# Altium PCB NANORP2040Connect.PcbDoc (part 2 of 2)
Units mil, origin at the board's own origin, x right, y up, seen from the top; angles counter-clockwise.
Board outline 1700 x 700 mil, 4 copper layers (TOP, GND, SIG, BOTTOM), stack 62.441 mil thick; 92 components, 78 nets, 400 pads, 196 vias.
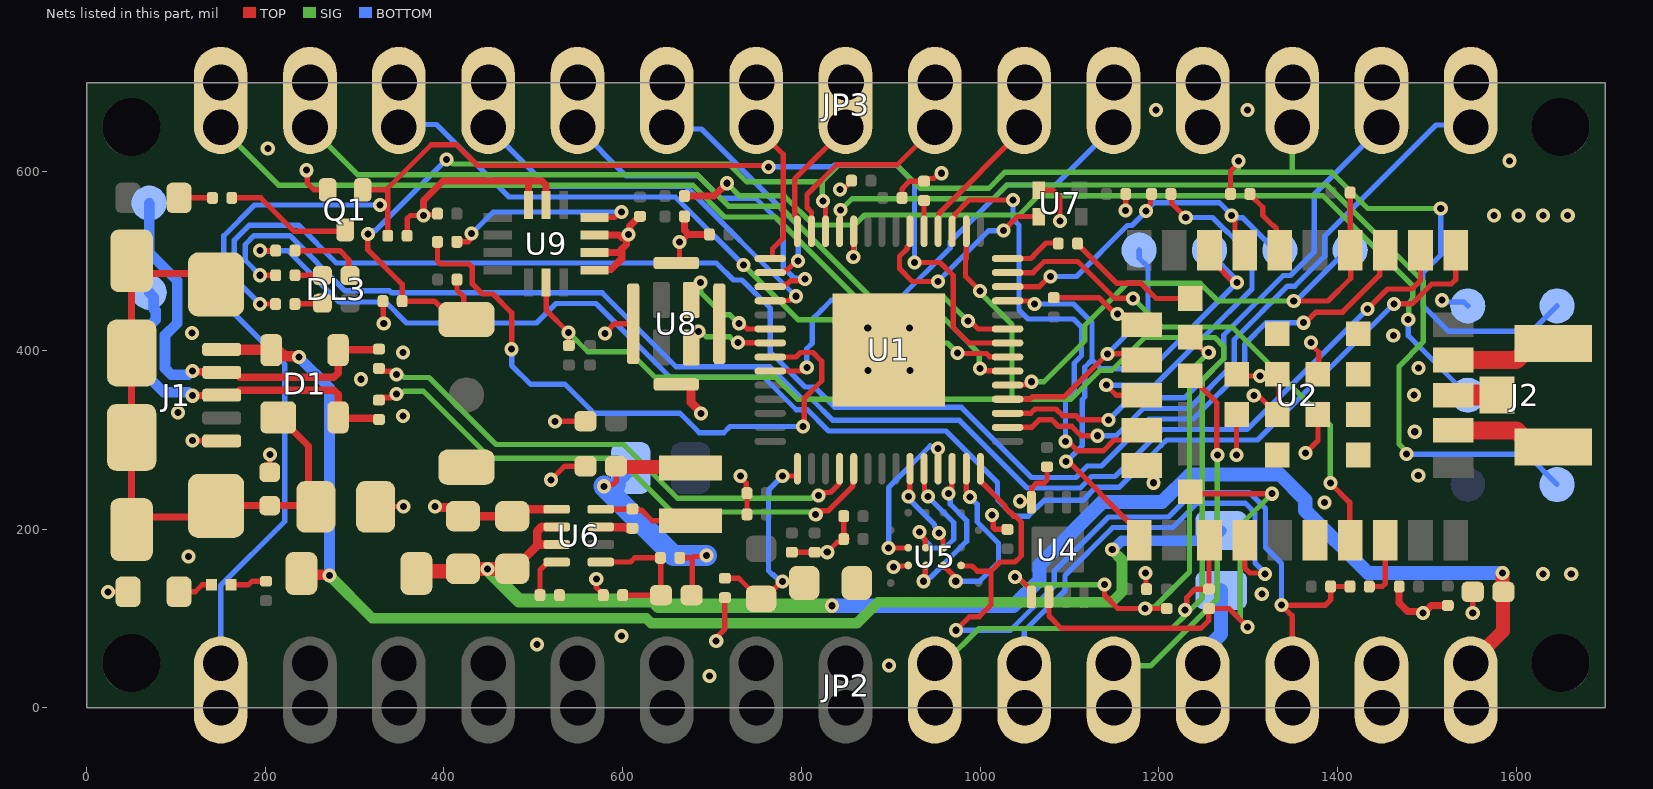
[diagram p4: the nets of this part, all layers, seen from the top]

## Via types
v1: diameter 15.75, hole 7.87, TOP to BOTTOM, tented both sides, 196 vias

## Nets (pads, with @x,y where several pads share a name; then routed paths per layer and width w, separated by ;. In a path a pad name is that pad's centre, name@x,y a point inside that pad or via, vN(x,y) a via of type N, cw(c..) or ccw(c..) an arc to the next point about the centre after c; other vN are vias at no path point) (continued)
A5/SCL~: JP2.9 R10.1 R17.1 U1.16 U2.3 U9.13 | length 1810
  TOP w5.91: U9.13@514.34,476.13 514.38,476.09 514.38,445.21 539.67,419.93 539.67,405.61 R10.1@539.76,405.51 ; U1.16@984.64,533.47 984.64,502.76 983.72,501.83 983.72,483.15 v1(1000.02,466.85) ; v1(1229.53,109.48) 1231.41,111.36 1231.41,123.54 1240.75,132.87 R17.1@1256.3,132.87 1256.3,187.01 U2.3@1256.89,187.6
  SIG w5.91: v1(539.57,420.03) 560.98,398.62 607.7,398.62 636.25,370.08 771.12,370.08 795.72,345.47 1035.82,345.47 ; JP2.9@949.41,50 959.84,50 998.7,88.86 1214.68,88.86 v1@1231.65,105.83 ; v1(1000.02,466.85) 1000.02,464.98 1035.82,429.17 1035.82,345.47 ; v1(1229.53,109.48) 1231.65,107.35 1233.17,107.35 1248.91,123.09 1248.91,366.96 1272.76,390.82 1272.76,404.68 1262.96,414.48 1184.35,414.48 1147.8,377.94 1134.42,377.94 1101.96,345.47 1035.82,345.47
A6: JP2.10 U2.4 | length 497.5
  TOP w5.91: U2.4@1296.26,187.6 1296.26,156.75 1302.12,150.89 1317.56,150.89 v1(1318.85,149.61)
  BOTTOM w5.91: JP2.10@1049.41,50 1049.41,85.73 1095.03,131.35 1095.03,148.15 1148.65,201.77 1215.75,201.77 1243.15,229.17 1296.85,229.17 1307.8,218.22 1307.8,162.22 1318.85,151.16 v1(1318.85,149.61)
A7: JP2.11 U2.34 | length 410.8
  TOP w5.91: U2.34@1235.23,371.65 1264.96,341.92 1264.96,283.69 v1(1265.64,283.01)
  SIG w5.91: JP2.11@1149.41,50 1152.36,47.05 1190.76,47.05 1260.72,117.01 1265.64,121.93 v1(1265.64,283.01)
ANT: J2.SIG U2.13 | length 49.2
  TOP w23.62: U2.13@1529.53,350 J2.SIG@1578.74,350
D2~: JP3.5 U1.37 | length 529.4
  TOP w5.91: U1.37@765.16,376.97 799.45,376.97 803.44,380.96 v1(806.1,380.96)
  BOTTOM w5.91: v1(806.1,380.96) 806.1,402.03 812.14,408.06 812.14,434.83 822.4,445.09 833.55,456.25 907.98,456.25 966.79,515.06 966.79,521.9 1030.04,585.16 1084.57,585.16 JP3.5@1149.41,650
D3~: JP3.6 U1.18 | length 156.4
  TOP w5.91: U1.18@953.15,533.47 953.52,533.84 953.52,553.01 1049.41,648.9 JP3.6@1049.41,650
D4~: JP3.7 U1.27 | length 217.6
  TOP w5.91: U1.27@811.41,533.47 811.41,554.79 806.3,559.91 806.3,574.58 839.68,607.97 907.38,607.97 JP3.7@949.41,650
D5~: JP3.8 U1.28 | length 141.4
  TOP w5.91: U1.28@795.67,533.47 795.67,547.78 792.52,550.92 792.52,591.92 849.41,648.81 JP3.8@849.41,650
D6~: JP3.9 U1.29 | length 166.7
  TOP w5.91: JP3.9@749.41,650 779.79,619.62 779.79,598.48 779.73,598.41 779.73,525.89 767.72,513.88 767.72,503.86 766.06,503.86 U1.29@765.16,502.95
D7~: JP3.10 U1.30 | length 268.9
  TOP w5.91: U1.30@765.16,487.21 779.47,487.21 782.42,490.16 784.23,490.16 794.25,500.18 v1(796.43,500.18)
  BOTTOM w5.91: JP3.10@649.41,650 651.49,647.91 688.27,647.91 796.43,539.75 v1(796.43,500.18)
D8~: JP3.11 U1.31 | length 395.3
  TOP w5.91: U1.31@765.16,471.46 779.47,471.46 782.42,474.41 784.23,474.41 787.95,478.13 802.43,478.13 v1(804.32,480.01)
  BOTTOM w5.91: JP3.11@549.41,650 603.94,595.47 684.78,595.47 709.75,570.5 748.98,570.5 779.73,539.75 779.73,516.51 ; 779.7,516.49 779.7,493.25 791.71,481.23 803.09,481.23 v1(804.32,480.01)
D9~: JP3.12 U1.32 | length 453.7
  TOP w5.91: U1.32@765.16,455.71 765.53,456.09 786.56,456.09 791.21,460.74 v1(793.88,460.74)
  BOTTOM w5.91: JP3.12@449.41,650 515.75,583.66 670.77,583.66 793.7,460.74 v1(793.88,460.74)
D10~: JP3.13 U1.7 | length 790.5
  TOP w5.91: v1(974.8,397.41) 975.56,396.65 1007.08,396.65 1010.64,393.09 1030.53,393.09 U1.7@1030.9,392.72
  SIG w5.91: v1(735.14,495.63) 796.18,434.59 834.84,434.59 860.93,408.5 963.72,408.5 v1(974.8,397.41)
  BOTTOM w5.91: JP3.13@349.41,650 352.36,652.95 391.5,652.95 472.61,571.85 658.92,571.85 v1(735.14,495.63)
D_N: R4.2 U1.46 | length 599.1
  TOP w5.91: v1(819.29,237.86) 821.95,237.86 825.24,241.14 832.46,241.14 842.53,251.21 842.53,267.34 U1.46@842.91,267.72
  TOP w6.3: R4.2@327.16,379.92 330.1,376.98 340.34,376.98 344.29,373.03 v1(346.85,373.03)
  SIG w5.91: v1(346.85,373.03) 348.73,371.15 353.96,371.15 355.23,369.88 383.2,369.88 458.21,294.87 601.2,294.87 661.41,234.66 811,234.66 812.31,235.98 817.41,235.98 v1(819.29,237.86)
D_P: R5.2 U1.47 | length 608.4
  TOP w5.91: v1(816.11,216.44) 818.77,216.44 822.87,220.53 829.94,220.53 857.69,248.28 857.69,251.58 858.28,252.17 858.28,267.34 U1.47@858.66,267.72
  TOP w6.3: R5.2@327.16,344.49 330.1,347.43 v1@340.34,347.43
  SIG w5.91: v1(346.85,351.38) 348.73,353.26 353.96,353.26 355.23,354.53 376.84,354.53 451.85,279.52 594.84,279.52 655.05,219.31 v1@808.98,219.31
GND: C1.1 C2.2 C3.1 C4.1 C5.2 C6.2 C7.2 C8.2 C9.1 C10.2 C11.2 C12.2 C13.2 C14.2 C15.2 C16.2 C17.1 C18.2 C21.2 C22.1 C23.1 C24.2 C25.1 C26.2 C27.2 C28.2 C30.2 C32.2 C33.1 DL1.C J1.5 J2.GND JP2.14 JP3.4 PB1.1 Q1.S R1.1 R3.1 R8.1 R23.1 TP_GND.X U1.GND U2.6 U2.12 U2.14 U2.26 U2.30 U2.GND1 U2.GND2 U2.GND3 U2.GND4 U2.GND5 U2.GND6 U2.GND7 U2.GND8 U2.GND9 U2.GND10 U2.GND11 U2.GND12 U4.4 U5.E4 U6.1 U7.2 U8.5 U9.1 U9.2 U9.3 U9.6 U9.7 | length 2255.1
  TOP w5.91: v1(24.01,129.92) DL1.C@46.26,129.92 ; v1(118.5,299.21) 118.7,299.02 150.98,299.02 J1.5@151.18,298.82 ; R1.1@205,263.7 205.06,263.76 205.06,283.41 v1(205.12,283.46) ; v1(246.06,601.83) 246.89,601 246.89,587.46 254.44,579.92 Q1.S@269.68,579.92 ; C1.1@323.46,225 323.86,225.39 v1(354.72,225.39) ; C2.2@331.56,455.25 332.06,454.75 332.06,430.61 v1(332.56,430.11) ; R23.1@358.72,528.49 358.72,547.72 362.18,551.18 v1(377.23,551.18) ; v1@377.23,552.17 391.73,552.17 C30.2@392.72,553.15 ; v1(519.69,255.31) 534.84,270.47 C3.1@558.46,270.47 ; v1(524.37,320.64) 524.48,320.76 558.35,320.76 C17.1@558.46,320.87 ; v1(570.47,144.49) 570.47,134.77 578.35,126.89 R8.1@578.35,126.18 ; v1(580.05,419.14) 580.05,419.23 590.94,430.12 611.65,430.12 U8.5@611.77,430 ; U8.5@660,497.91 663.62,501.53 v1(663.62,521.49) 665.24,521.49 673.75,530 ; v1(704.72,74.8) 704.72,78.74 714.42,88.44 C8.2@714.42,123.39 ; v1(731.78,259.64) 731.78,257.83 738.44,251.17 738.44,241.07 C18.2@739.21,240.29 739.16,240.24 739.16,216.68 C13.2@739.11,216.63 ; C5.2@789.37,174.21 C6.2@814.96,174.21 v1(829.02,174.21) 840.18,185.37 844.31,185.37 847.44,188.51 C33.1@847.44,188.98 ; v1(843.36,580.25) 845.25,582.14 848.73,582.14 856.21,589.62 C10.2@856.21,590.09 ; C24.2@847.44,214.57 C33.1@847.44,188.98 ; C33.1@851.38,188.98 C33.1@847.44,188.98 ; v1(903.3,157.57) 904.66,158.92 919.16,158.92 U5.E4@919.68,159.45 ; C11.2@912.79,570.87 912.79,580.78 913.51,581.49 913.51,581.81 921.27,589.57 R3.1@937.4,589.57 940.41,592.58 948.18,592.58 954.03,598.43 v1(956.69,598.43) ; v1(1013.63,215.65) 1014.89,214.4 1014.89,201.65 1016.73,199.8 C27.2@1030.71,199.8 ; v1(1044.82,231.31) 1055.31,231.31 1055.31,233.27 1057.48,231.1 U4.4@1057.48,230.12 1058.04,230.68 1058.04,246.37 1063.25,251.57 1071.54,251.57 1075,255.03 C12.2@1075,269.92 ; U7.2@1065.85,579.39 1081.6,579.39 1089.67,571.32 v1(1089.67,544.94) ; C7.2@1082.55,459.17 1114.58,459.17 1133.21,459.17 1151.67,440.7 v1(1153.96,440.7) 1155.09,439.57 1170.27,439.57 U2.26@1181.1,428.74 ; v1(1163.07,556.62) 1163.12,556.67 1163.12,574.75 C14.2@1163.17,574.8 ; U2.30@1181.1,271.26 1183.6,271.26 1194.43,260.43 v1(1194.43,251.97) ; v1(1185.43,151.18) 1185.92,150.69 1185.92,133.37 C26.2@1186.42,132.87 ; v1(1287.29,283.01) 1287.22,283.08 1287.22,327.98 U2.GND11@1287.6,328.35 ; U2.GND12@1287.6,373.62 1289.67,371.55 v1(1313.49,371.55) ; v1(1306.45,349.61) 1308.33,347.72 1313.49,347.72 U2.GND8@1332.87,328.35 1335.04,330.52 1335.04,371.45 U2.GND9@1332.87,373.62 ; v1(1364.54,285.41) 1378.34,299.21 1378.34,328.15 U2.GND5@1378.15,328.35 ; v1(1370.7,409.22) 1370.7,406.56 1379.15,398.1 1379.15,374.63 U2.GND6@1378.15,373.62 ; v1(1551.57,106.3) C25.1@1551.57,129.92
  TOP w7.87: v1(377.23,551.18) 377.23,552.17 377.23,567.98 398.96,589.71 494.65,589.71 ; U9.7@494.65,562.75 494.65,589.71 ; U9.6@514.34,562.75 514.34,585.1 509.73,589.71 494.65,589.71 ; U9.1@568.47,489.91 569.46,490.89 587.14,490.89 598.98,502.73 598.98,513.45 ; U9.2@568.47,509.6 595.13,509.6 598.98,513.45 ; U9.3@568.47,529.28 596.03,529.28 599.09,526.22 v1@604.1,526.22 ; v1(606.42,529.69) 607.92,531.2 607.92,539.31 616.65,548.03 617.24,548.03 C32.2@619.4,550.2 ; v1@607.57,529.69 v1@604.1,526.22 ; C28.2@669.13,550.11 669.13,534.61 673.75,530 C21.2@697.05,530 ; C15.2@1469.25,135.87 1469.25,117.36 1478.81,107.81 1494.16,107.81 v1(1495.67,106.3) 1496.79,106.3 1505.12,114.62 C16.2@1523.62,114.62 ; 598.98,513.45 604.1,518.57 v1@604.1,526.22
  TOP w9.84: v1(390.16,225.39) 391.29,224.26 411.56,224.26 C23.1@421.26,214.57 C4.1@476.38,214.57 484.05,222.24 U6.1@526.18,222.24 ; U8.5@660,362.09 674.39,362.09 676.35,360.12 676.35,342.4 687.75,331.01 v1(687.75,329.72)
  TOP w20: U2.12@1529.53,310.63 1600.4,310.63 1619.1,291.93 J2.GND@1641.73,291.93 ; U2.14@1529.53,389.37 1600.4,389.37 1619.1,408.07 J2.GND@1641.73,408.07
  BOTTOM w5.91: v1(1516.99,456.3) 1518.88,454.42 1541.58,454.42 TP_GND.X@1546,450
  other v1: 697.24,35.43 898.03,47.24 504.33,70.87 598.82,80.6 1315.42,127.5 1630.31,149.61 1661.81,149.61 114.17,169.49 1385.76,229.87 1490.55,260.24 1486.63,309.08 354.33,326.77 102.36,330.71 1485.63,350.39 307.08,367.85 874.41,377.57 921.65,377.57 1490.87,380.59 354.33,397.64 1462.6,416.93 118.05,419.43 874.34,425.23 921.16,425.23 1575.19,551.18 1602.75,551.18 1630.31,551.18 1657.87,551.18 1592.91,612.4 202.75,626.18 1197.24,669.29 1299.6,669.29
GPIO0: TP_GPIO0.X U1.4 U2.27 | length 313.3
  TOP w5.91: U1.4@1030.9,345.47 1055.91,345.47 1058.77,348.33 1094.53,348.33 v1(1142.49,396.29) 1174.18,396.29 U2.27@1181.1,389.37
  BOTTOM w5.91: v1(1142.49,396.29) 1188.17,441.96 1188.17,493.32 1178.15,503.34 TP_GPIO0.X@1178.15,512.4
INT1: R24.2 U1.36 | length 703.8
  TOP w5.91: R24.2@392.72,521.65 392.72,500.33 396.18,496.87 428.04,496.87 431.5,493.41 431.5,474.88 443.11,463.27 454.71,463.27 475.74,442.24 v1(475.74,401.45) ; U1.36@765.16,392.72 793.95,392.72 798.93,397.69 813.03,397.69 822.83,387.89 822.83,366.14 803.15,346.46 803.15,316.32 v1(801.79,314.96)
  BOTTOM w5.91: v1(475.74,401.45) 475.74,383.29 496.83,362.2 535.43,362.2 567.91,329.72 664.08,329.72 685.82,307.99 713.15,307.99 720.12,314.96 v1(801.79,314.96)
LEDB: R13.2 U2.17 | length 1625.6
  TOP w5.91: v1(194.23,484.25) R13.2@211.61,484.25 ; v1(1433.73,446.46) 1456.25,468.98 1483.51,468.98 1493.11,478.58 U2.17@1493.11,512.4
  BOTTOM w5.91: v1(194.23,484.25) 177.5,500.98 177.5,518.75 187.3,528.55 227.44,528.55 289.19,466.8 338.92,466.8 341.15,464.57 577.2,464.57 659.88,381.89 764.8,381.89 801.22,345.47 811.64,345.47 835.26,321.85 976.93,321.85 1052.72,246.06 1112.21,246.06 1125,258.86 1151.12,258.86 1203.82,311.55 1298.82,311.55 v1(1433.73,446.46)
LEDG: R14.2 U2.16 | length 1651
  TOP w5.91: v1(194.23,511.82) R14.2@211.61,511.82 ; v1(1463.18,452.25) 1483.48,452.25 1505.64,474.41 1527.56,474.41 1532.48,479.33 U2.16@1532.48,512.4
  BOTTOM w5.91: v1(194.23,511.82) 225.12,511.82 282.67,454.27 334.74,454.27 358.11,430.91 503.72,430.91 525.57,452.76 570.27,452.76 652.95,370.08 757.87,370.08 794.29,333.66 806.75,333.66 830.37,310.04 961.95,310.04 1019.68,252.3 1019.68,233.27 1028.09,224.86 1028.09,224.38 1037.89,214.58 1053.99,214.58 1071.69,232.28 1115.13,232.28 1129.9,247.05 1156.02,247.05 1202.9,293.93 1208.71,299.74 1310.68,299.74 1444.09,433.16 v1(1463.18,452.25)
LEDR: R15.2 U2.18 | length 1675.5
  TOP w5.91: v1(194.09,451.97) R15.2@211.48,451.97 ; v1(1362.18,431.12) 1364.19,431.12 1375.98,442.91 1405.9,442.91 1447.35,484.36 1447.35,506.01 U2.18@1453.74,512.4
  BOTTOM w5.91: v1(194.09,451.97) 165.35,480.71 165.35,523.62 182.1,540.36 237.01,540.36 279.34,498.03 704.72,498.03 723.86,478.9 733.7,478.9 765.16,447.44 765.16,398.24 804.31,359.09 814.73,359.09 837.2,336.61 978.87,336.61 1057.61,257.87 1107.32,257.87 1120.11,270.67 1136.18,270.67 1188.88,323.36 1238.72,323.36 1296.44,381.09 1296.44,407.22 1320.33,431.1 v1(1362.18,431.12)
NetC1_2: C1.2 D1.1 J1.M1 J1.M2 J1.M3 J1.M4 J1.M5 J1.M6 R1.2 | length 742.7
  TOP w7.87: J1.M1@144.88,473.92 132.65,486.14 64.64,486.14 J1.M2@50.39,500.39 J1.M3@50.39,199.61 64.64,213.86 132.65,213.86 145.09,226.3 255.24,226.3 C1.2@256.54,225 248.45,233.08 248.45,293.2 216.46,325.2 D1.1@214.49,325.2
NetC3_2: C3.2 C20.2 L2.2 R6.2 SJ4.2 | length 377.2
  TOP w5.91: v1(579.13,248.03) 581.01,249.91 589.17,249.91 592.72,253.46 C3.2@592.72,270.47 ; R6.2@663.92,167.98 677.95,167.98 ; C20.2@677.17,126.18 677.95,126.97 677.95,167.98 ; v1(693.75,170.34) 692.81,169.4 679.38,169.4 677.95,167.98
  TOP w15.75: C3.2@593.7,269.49 675,269.49 L2.2@675.98,268.5
  BOTTOM w15.75: v1(579.13,248.03) 579.75,248.65 595.23,248.65 595.23,254.68 SJ4.2@609.05,268.5
  BOTTOM w23.62: v1(579.13,248.03) 656.82,170.34 v1(693.75,170.34)
NetC8_1: C8.1 C9.2 L1.1 U1.43 | length 268.8
  TOP w5.91: C8.1@714.42,145.04 729.97,145.04 752.97,122.05 L1.1@755,122.05 758.54,122.05 777.85,141.36 v1(779.03,141.36) C9.2@804.74,141.36 ; v1(779.1,259.49) 794.76,259.49 795.67,260.4 U1.43@795.67,267.72 ; C9.2@804.74,139.39 C9.2@807.09,141.73
  BOTTOM w5.91: v1(779.03,141.36) 776.36,141.36 768.44,149.28 767.46,149.28 763.29,153.45 763.29,180.22 763.29,243.68 v1(779.1,259.49)
NetC19_1: C19.1 L2.1 U6.8 | length 106.2
  TOP w5.91: U6.8@575.39,222.24 575.59,222.44 610.63,222.44 C19.1@610.83,222.64 612.13,221.34 621.18,221.34 633.07,209.45 L2.1@675.98,209.45
NetC19_2: C19.2 U6.7 | length 36.1
  TOP w9.45: U6.7@575.39,202.56 575.59,202.36 603.15,202.36 604.53,200.98 C19.2@610.83,200.98
NetC20_1: C20.1 R6.1 R8.2 U6.5 | length 152.6
  TOP w5.91: U6.5@575.39,163.19 608.76,163.19 613.55,167.98 R6.1@642.26,167.98 642.59,167.65 642.59,127.43 641.34,126.18 R8.2@600,126.18
NetC22_2: C22.2 U6.4 | length 50.5
  TOP w5.91: C22.2@507.48,126.18 507.48,154.33 516.34,163.19 U6.4@526.18,163.19
NetDL1_A: DL1.A SJ2.1 | length 39.7
  TOP w5.91: DL1.A@103.34,129.92 121.52,129.92 129.39,137.8 SJ2.1@139.76,137.8
NetDL2_C: DL2.C R25.1 | length 37.4
  TOP w5.91: DL2.C@103.35,570.87 R25.1@140.75,570.87
NetDL3_2: DL3.2 R15.1 | length 29.1
  TOP w5.91: R15.1@233.13,451.97 233.62,452.46 261.32,452.46 DL3.2@261.81,452.95
NetDL3_3: DL3.3 R13.1 | length 28.6
  TOP w5.91: R13.1@233.27,484.25 233.37,484.15 261.71,484.15 DL3.3@261.81,484.05
NetDL3_4: DL3.4 R14.1 | length 82.2
  TOP w5.91: R14.1@233.27,511.82 283.45,511.82 293.31,501.97 293.31,484.44 DL3.4@292.91,484.05
NetJP2_12: JP2.12 SJ1.2 | length 90.1
  BOTTOM w15.75: JP2.12@1249.41,50 1249.41,61.97 1270,82.56 SJ1.2@1270,131.54
NetQ1_D: Q1.D R25.2 | length 143.1
  TOP w5.91: R25.2@162.4,570.87 194.88,570.87 232.28,533.46 287.8,533.46 Q1.D@289.37,535.04
NetR2_1: R2.1 SJ2.2 | length 39.1
  TOP w5.91: SJ2.2@163.39,137.8 181.28,137.8 185.34,141.85 200.67,141.85 R2.1@200.79,141.73
NetR3_2: R3.2 U1.19 | length 34.4
  TOP w5.91: U1.19@937.4,533.47 R3.2@937.4,567.91
NetR18_2: R18.2 U2.36 | length 151.8
  TOP w5.91: R18.2@1109.25,519.68 1109.25,519.09 1153.17,475.18 1180.33,475.18 1197.24,458.27 U2.36@1235.23,458.27
NetR20_1: R20.1 U2.8 | length 67.7
  TOP w5.91: R20.1@1435.79,135.87 1450.28,135.87 1453.74,139.33 U2.8@1453.74,187.6
NetR22_1: R22.1 U2.28 | length 420
  TOP w5.91: v1@1140.53,360.38 v1(1141.35,361.2) 1152.55,350 U2.28@1181.1,350 ; R22.1@1213.66,574.65 R22.1@1213.66,579.41 ; R22.1@1213.66,574.76 R22.1@1213.66,575.24 1214.61,574.29 1214.61,564.53 v1(1230.31,548.82)
  BOTTOM w5.91: v1(1141.35,361.2) 1195.82,361.2 1250.69,416.07 1251.54,416.07 1304.53,469.05 1304.53,504.53 1277.29,532.36 ccw(c1256.89,512.4) 1273.53,535.59 1260.24,548.82 v1(1230.31,548.82)
NetR24_1: R24.1 U9.4 | length 234.3
  TOP w5.91: R24.1@414.37,521.65 427.22,521.65 428.8,523.23 428.8,529.08 v1(430.68,530.96) ; U9.4@568.47,548.97 590.67,548.97 596.82,555.12 v1(598.68,555.12)
  BOTTOM w5.91: v1(430.68,530.96) 431.03,530.96 455.19,555.12 v1(598.68,555.12)
NetR28_1: R28.1 U2.21 | length 77.1
  TOP w5.91: R28.1@1302.17,575.24 1302.17,574.65 1316.45,560.36 1316.45,551.15 1327.71,539.88 1328.36,539.88 1331.82,536.42 1331.82,516.21 U2.21@1335.63,512.4
NetU1_20: U1.20 U7.3 | length 238.7
  TOP w5.91: U1.20@921.65,533.47 921.65,519.15 918.7,516.2 918.7,514.29 909.9,505.5 909.9,491.63 924.17,477.36 v1(952.76,477.36) ; v1(1026.14,534.22) 1041.94,550.02 1065.7,550.02 U7.3@1065.85,549.87
  BOTTOM w5.91: v1(952.76,477.36) 1009.41,534.01 1025.93,534.01 v1(1026.14,534.22)
PDMCLK: U1.35 U8.3 | length 106.7
  TOP w5.91: U8.3@676.73,403.43 676.73,412.95 v1(685.04,421.26) ; v1(728.9,408.9) 729.11,408.68 764.94,408.68 U1.35@765.16,408.46
  SIG w5.91: v1(685.04,421.26) 687.7,421.26 693.61,415.35 719.78,415.35 726.23,408.9 v1(728.9,408.9)
PDMDIN: U1.34 U8.4 | length 130.9
  TOP w5.91: U8.4@676.73,456.57 676.73,467.2 685.91,476.38 v1(687.01,476.38) ; v1(730.46,430.49) 733.12,430.49 739.41,424.21 U1.34@765.16,424.21
  SIG w5.91: v1(687.01,476.38) 687.44,475.94 687.44,464.96 712.27,440.14 719.78,440.14 729.43,430.49 v1(730.46,430.49)
QSPI_CSn: JP2.13 R19.1 R20.2 U1.56 U5.B4 | length 990.4
  TOP w5.91: v1(973.07,86.89) 988.23,102.05 999.05,102.05 1012.32,115.33 1012.32,152.95 ; U5.B4@978.74,159.45 979.27,158.92 991.03,158.92 997,152.95 1003.89,152.95 1012.32,152.95 ; U1.56@1000.39,267.72 1000.39,253.94 1028.09,226.24 1028.09,224.38 1037.89,214.58 1039.39,214.58 1046.26,207.72 1046.26,170.24 1039.21,163.19 1022.56,163.19 1012.32,152.95 ; JP2.13@1349.41,50 1349.41,103.07 1337.65,114.83 v1(1337.65,114.98) 1386.63,114.98 1392.48,120.83 R19.1@1392.48,135.87 R20.2@1414.13,135.87
  BOTTOM w5.91: v1(973.07,86.89) 1033.87,86.89 1083.22,136.24 1083.22,153.04 1143.76,213.58 1210.86,213.58 1238.26,240.98 1301.74,240.98 1319.61,223.12 1319.61,179.4 1337.6,161.41 1337.6,115.03 v1(1337.65,114.98)
QSPI_SCK: U1.52 U5.D3 | length 165.2
  TOP w5.91: v1(932.32,196.91) 932.32,194.25 938.84,187.73 938.84,179.66 U5.D3@939.37,179.13 ; U1.52@937.4,267.72 937.78,267.34 937.78,242.92 941.55,239.15 v1(941.55,236.48)
  BOTTOM w5.91: v1(932.32,196.91) 932.32,194.25 937.2,189.36 937.2,188.76 947.01,178.96 960.87,178.96 970.67,188.76 970.67,207.37 v1(941.55,236.48)
QSPI_SD0: U1.53 U5.E3 | length 188.4
  TOP w5.91: v1(897.71,178.98) 897.79,179.05 919.6,179.05 U5.E3@919.68,179.13 ; v1(953.08,290.35) 953.11,290.32 953.11,267.75 U1.53@953.15,267.72
  BOTTOM w5.91: v1(897.71,178.98) 897.71,246.78 944.3,293.37 945.43,292.24 951.19,292.24 v1(953.08,290.35)
QSPI_SD1: U1.55 U5.C4 | length 199.9
  TOP w5.91: U5.C4@959.05,159.45 970.95,147.55 970.95,143.62 v1(972.83,141.73) ; U1.55@984.64,267.72 984.64,242.82 988.58,238.88 v1(988.58,236.22)
  BOTTOM w5.91: v1(972.83,141.73) 999.64,141.73 1020.67,162.75 1020.67,184.32 996.9,208.09 996.9,227.84 v1(988.58,236.22) v1(988.58,236.22)
QSPI_SD2: U1.54 U5.D4 | length 176.8
  TOP w5.91: v1(936.81,141.73) 936.81,144.4 938.84,146.43 938.84,158.92 U5.D4@939.37,159.45 ; v1(964.96,240.16) 964.96,242.82 968.52,246.38 968.52,267.34 U1.54@968.9,267.72
  BOTTOM w5.91: v1(936.81,141.73) 939.47,141.73 943.63,145.89 944.5,145.89 985.09,186.48 985.09,209.65 966.84,227.9 966.84,238.27 v1(964.96,240.16)
QSPI_SD3: U1.51 U5.C3 | length 105.5
  TOP w5.91: v1(919.9,236.61) 921.27,237.99 921.27,267.34 U1.51@921.65,267.72 ; v1(953.94,195.7) 953.94,193.03 958.53,188.44 958.53,179.66 U5.C3@959.05,179.13
  BOTTOM w5.91: v1(919.9,236.61) 919.9,234.47 949.05,205.32 949.05,203.25 953.94,198.36 v1(953.94,195.7)
RESETN: C2.1 JP3.3 PB1.2 R12.1 R28.2 TP_RESETN.X U1.26 | length 1960.7
  TOP w5.91: v1(314.75,530.33) 314.75,512.56 353.22,474.09 C2.1@353.22,455.25 389.24,455.25 409.76,434.72 PB1.2@425.2,434.72 422.22,437.69 422.22,459.81 414.57,467.46 R12.1@414.57,479.37 ; v1(824.02,567.24) 824.02,564.58 827.16,561.44 U1.26@827.16,533.47 ; R28.2@1280.51,575.24 1280.51,600.68 1289.37,609.54 v1(1289.37,612.2)
  SIG w5.91: v1(402.6,613.64) 405.27,613.64 410.19,608.72 718.86,608.72 738.66,588.92 823.27,588.92 ; v1(824.02,567.24) 823.27,567.99 823.27,588.92 ; v1(1289.37,612.2) 1289.37,599.41 ; JP3.3@1349.41,650 1349.41,599.41 ; v1(1515.75,559.06) 1434.08,559.06 1393.73,599.41 1349.41,599.41 ; 823.27,588.92 841.94,607.59 906.82,607.59 932.71,581.69 1009.87,581.69 1027.59,599.41 1289.37,599.41 ; 1289.37,599.41 1349.41,599.41
  BOTTOM w5.91: v1(314.75,530.33) 317.41,530.33 321.06,533.98 322.95,533.98 v1(402.6,613.64) ; v1(1515.75,559.06) 1515.75,507.07 1495.95,487.28 1495.95,450.18 1524.68,421.46 1617.46,421.46 TP_RESETN.X@1646,450
RSTN_NINA: R7.1 TP_RST.X U1.5 U2.19 | length 642.9
  TOP w5.91: U1.5@1030.9,361.22 1031.28,361.6 1051.67,361.6 1055.14,365.06 v1(1057.8,365.06) ; v1(1351.21,455.31) 1389.41,455.31 1415,480.9 U2.19@1415,512.4 ; U2.19@1414.37,512.4 R7.1@1414.37,576.69
  SIG w5.91: v1(1057.8,365.06) 1071.75,365.06 1117.26,410.57 1117.26,427.93 1164.5,475.18 1246.59,475.18 1266.46,455.31 v1(1351.21,455.31)
  BOTTOM w5.91: v1(1351.21,455.31) 1353.88,455.31 1410.96,512.4 TP_RST.X@1414.37,512.4
RX: JP3.2 U1.3 | length 614.2
  TOP w5.91: U1.3@1030.9,329.72 1056.87,329.72 1061.57,334.42 1085.21,334.42 1092.71,326.93 1107.61,326.93 1112.12,322.42 v1(1143.9,322.42)
  BOTTOM w5.91: v1(1143.9,322.42) 1168.46,346.99 1228.93,346.99 1272.82,390.87 1272.82,417.29 1339.39,483.86 1347.45,483.86 1374.01,510.42 1374.01,574.6 JP3.2@1449.41,650
SCL_CRYPTO: R17.2 U2.31 U4.6 | length 533.9
  TOP w5.91: U4.6@1077.16,124.21 1077.16,102.76 1090.82,89.1 1247.19,89.1 1256.03,97.94 1256.03,110.95 R17.2@1256.3,111.22 1256.39,111.13 1278.63,111.13 v1(1299.21,90.55) ; U2.31@1235.23,241.73 1237.25,239.7 v1(1326.68,239.7)
  SIG w5.91: v1(1299.21,90.55) 1299.21,91.06 1291.34,98.93 1291.34,204.36 v1(1326.68,239.7)
SDA_CRYPTO: R16.2 U2.35 U4.5 | length 572.3
  TOP w5.91: v1(1039.15,146.46) 1041.03,144.57 1044.6,144.57 1057.48,131.69 U4.5@1057.48,124.21 ; v1(1139.25,137.91) 1139.25,126.16 1154.19,111.22 v1(1184.94,111.22) R16.2@1209.05,111.22 ; U2.35@1235.23,414.96 1250.56,399.63 1254.15,399.63 v1(1256.03,397.75)
  SIG w5.91: v1(1039.15,146.46) 1041.81,146.46 1050.35,137.91 v1(1139.25,137.91) ; v1(1184.94,111.22) 1186.53,112.81 1195.2,112.81 1234.59,152.2 1234.59,376.3 v1(1256.03,397.75)
SPI1_ACK/UART1_CTS: U1.13 U2.7 | length 580.4
  TOP w5.91: U1.13@1030.9,487.21 1059.53,487.21 1071.92,499.59 1109.48,499.59 1150.63,458.45 v1(1171.44,458.45) ; v1(1392.1,251.7) 1413.78,230.01 1413.78,188.19 U2.7@1414.37,187.6
  SIG w5.91: v1(1171.44,458.45) 1203.59,426.29 1282.41,426.29 1392.1,316.61 v1(1392.1,251.7)
SPI1_CIPO/UART1_TX: TP_TX.X U1.11 U2.1 U2.23 | length 702.6
  TOP w5.91: U1.11@1030.9,455.71 1031.28,455.33 1054.81,455.33 1058.16,451.98 v1(1060.83,451.98) ; v1(1096.46,275.59) 1098.34,273.71 1101.57,273.71 1134.44,240.83 1134.44,240.16 1178.15,196.46 U2.1@1178.15,187.6 ; U2.23@1256.89,512.4 1256.89,503.54 1273.62,486.81 1273.62,486.09 1281.85,477.86 1285.91,477.86 v1(1287.79,475.98)
  BOTTOM w5.91: v1(1060.83,451.98) 1104.7,451.98 1125.3,431.38 1125.3,389.27 1117.28,381.24 1117.28,347.98 1114.59,345.3 1114.59,293.53 1096.66,275.59 v1(1096.46,275.59) ; 1125.98,389.13 1135.56,379.55 1191.37,379.55 v1(1287.79,475.98) 1287.79,478.64 1256.89,509.55 TP_TX.X@1256.89,512.4
SPI1_COPI/UART1_RTS: R18.1 U1.14 | length 64.4
  TOP w5.91: U1.14@1030.9,502.95 1057.02,502.95 1060.48,506.41 1060.48,506.78 1074.04,520.34 1086.94,520.34 R18.1@1087.6,519.68
SPI1_CS/UART1_RX: R22.2 TP_RX.X U1.12 U2.22 | length 431.5
  TOP w5.91: U1.12@1030.9,471.46 1066.59,471.46 1078,482.86 v1(1078.85,482.86) ; v1(1185.84,556.39) 1185.84,559.05 1190.83,564.04 1190.83,574.6 R22.2@1192.01,575.79 ; v1(1281.42,551.34) 1281.42,548.68 1285.43,544.67 1285.43,523.23 U2.22@1296.26,512.4
  BOTTOM w5.91: v1(1078.85,482.86) 1107.84,482.86 1164.86,539.88 1170,539.88 1185.84,555.72 v1(1185.84,556.39) 1195,565.55 1267.79,565.55 1281.42,551.92 v1(1281.42,551.34) ; v1@1281.87,551.63 v1@1284.5,548.28 ; v1@1286.55,548.71 1293.96,548.71 1330.27,512.4 TP_RX.X@1335.63,512.4
SPI1_SCK: U1.17 U2.29 | length 530
  TOP w5.91: U1.17@968.9,533.47 968.9,547.78 971.85,550.73 971.85,552.54 987.73,568.43 v1(1036.97,568.43) ; v1(1095.79,298.38) 1098.41,298.38 1108.93,287.86 1138.26,287.86 1150.2,299.8 1170.27,299.8 U2.29@1181.1,310.63
  BOTTOM w5.91: v1(1036.97,568.43) 1036.97,547.05 1043.75,540.27 1043.75,445.39 1053.9,435.25 1104.73,435.25 1113.49,426.48 1113.49,394.16 1105.47,386.14 1105.47,352.88 1095.79,343.2 v1(1095.79,298.38)
SPICLK~: JP2.1 Q1.G R23.2 U1.8 | length 1711.1
  TOP w5.91: Q1.G@309.06,579.92 337.07,579.92 ; v1(328.29,562.99) 330.95,562.99 336.05,557.88 337.07,557.88 ; R23.2@337.07,528.49 337.07,554.2 337.07,557.88 ; v1(763.06,605.65) 761.59,607.12 437.34,607.12 414.08,630.37 385.77,630.37 337.07,581.67 337.07,579.92 ; v1(926.63,498.56) 955.22,498.56 970,483.79 970,425.88 987.41,408.46 U1.8@1030.9,408.46 ; 337.07,557.88 337.07,579.92
  BOTTOM w5.91: JP2.1@150,50 150,136.98 221.85,208.83 221.85,384.45 153.54,452.76 153.54,528.51 188.02,562.99 v1(328.29,562.99) ; v1(763.06,605.65) 834.96,605.65 836.9,607.59 906.37,607.59 926.63,587.33 v1(926.63,498.56)
SPIRX~: JP3.15 U1.6 | length 1003.3
  TOP w5.91: v1(1000.15,379.92) 1002.03,378.04 1006.17,378.04 1006.87,377.35 1030.53,377.35 U1.6@1030.9,376.97
  SIG w5.91: JP3.15@150,650 214.9,585.1 678.45,585.1 714,549.55 771.04,549.55 871.78,448.82 947.06,448.82 999.01,396.87 999.01,381.07 v1(1000.15,379.92)
SPITX~: JP3.14 U1.9 | length 874.4
  TOP w5.91: v1(986.73,432.81) 989.39,432.81 997.99,424.21 U1.9@1030.9,424.21
  SIG w5.91: JP3.14@250,650 303.09,596.91 683.35,596.91 718.89,561.37 775.94,561.37 876.67,460.63 958.91,460.63 v1(986.73,432.81)
SWCLK: R11.1 TP_SWCLK.X U1.24 | length 1113.9
  TOP w5.91: v1(858.14,504.5) 858.4,504.76 858.4,533.21 U1.24@858.66,533.47
  TOP w7.87: R11.1@669.12,572.82 702.27,572.82 v1(716.68,587.24)
  SIG w5.91: v1(716.68,587.24) 730.74,573.18 780.83,573.18 813.44,540.56 859.59,540.56 ; v1(858.14,504.5) 859.59,505.95 859.59,540.56 ; v1(1479.33,434.68) 1479.91,435.26 1479.91,453.15 1484.25,457.49 1484.25,472.72 1383.62,573.35 1065.56,573.35 1043.9,551.7 870.72,551.7 859.59,540.56
  BOTTOM w5.91: v1(1479.33,434.68) 1479.33,416.67 1488.45,407.55 TP_SWCLK.X@1546,350
SWDIO: TP_SWDIO.X U1.25 | length 1123.4
  TOP w5.91: U1.25@842.91,533.47 843.29,533.84 843.29,556.51 v1(844.07,557.3)
  SIG w5.91: v1(844.07,557.3) 856.66,569.88 1014.76,569.88 1030.04,585.16 1388.51,585.16 1496.06,477.61 1496.06,409.45 1468.9,382.28 1468.9,295.27 1477.5,286.67 v1(1477.5,284.01)
  BOTTOM w5.91: v1(1477.5,284.01) 1611.99,284.01 TP_SWDIO.X@1646,250
TX: JP3.1 U1.2 | length 703.2
  TOP w5.91: U1.2@1030.9,313.98 1057.82,313.98 1066.46,322.61 1080.32,322.61 1087.82,315.12 1102.72,315.12 1113.24,304.6 v1(1131.33,304.6)
  BOTTOM w5.91: v1(1131.33,304.6) 1152.19,304.6 1182.77,335.18 1233.83,335.18 1284.63,385.98 1284.63,412.4 1344.28,472.05 1352.34,472.05 1385.82,505.53 1385.82,527.79 1510.55,652.52 1546.89,652.52 JP3.1@1549.41,650
USB_N: D1.3 D-.X J1.2 R4.1 | length 477.7
  TOP w8.27: v1(118.5,376.97) 119.19,376.28 150.49,376.28 J1.2@151.18,375.59 165.74,375.59 171.45,369.88 215.08,369.88 276.58,369.88 281.42,374.72 D1.3@281.42,400.39 ; D1.3@282.6,401.57 283.2,400.98 326.57,400.98 R4.1@327.16,401.57
  BOTTOM w11.81: D-.X@70,565 70,509.54 101.5,478.05 101.5,430.71 87.68,416.9 87.68,379.95 94.6,373.03 113.5,373.03 117.44,376.97 v1(118.5,376.97)
USB_P: D1.2 D+.X J1.3 R5.1 | length 397.6
  TOP w8.27: v1(118.5,349.41) 118.8,349.7 165.45,349.7 171.45,355.71 209.21,355.71 276.58,355.71 281.42,350.86 D1.2@281.42,325.2 ; D1.2@283.78,322.83 284.96,324.01 325.98,324.01 R5.1@327.16,322.83
  BOTTOM w11.81: D+.X@70,465 75.27,459.73 75.27,446.49 77.46,444.3 77.46,434.52 68,425.05 68,371.8 86.45,353.35 113.5,353.35 117.44,349.41 v1(118.5,349.41)
VIN: C4.2 C23.2 C25.2 D2.C JP2.15 U6.2 U6.3 | length 1601.1
  TOP w9.84: C4.2@476.38,155.51 478.35,155.51 505.71,182.87 U6.3@526.18,182.87 ; 504.5,181.66 504.5,197.53 509.53,202.56 U6.2@526.18,202.56
  TOP w15.75: D2.C@369.09,150.39 371.65,152.95 418.7,152.95 C23.2@421.26,155.51 421.35,155.42 476.29,155.42 C4.2@476.38,155.51 ; JP2.15@1549.41,50 1585.58,86.17 1585.58,126.38 1585.82,126.63 C25.2@1585.82,129.92 ; C25.2@1583.66,132.48 1584.02,132.48 1585,133.46 v1(1585,150.75)
  SIG w15.75: v1(448.79,155.42) 484.13,120.08 634.36,120.08 640.15,114.29 v1(834.32,114.29)
  BOTTOM w15.75: v1(834.32,114.29) 1037.6,114.29 1066.48,143.17 1066.48,159.97 1136.83,230.31 1203.93,230.31 1234.97,261.36 1335.65,261.36 1364.11,232.9 1364.11,220.9 1434.26,150.75 v1(1585,150.75)
VUSB: D1.4 D2.A J1.1 SJ1.1 | length 1487.9
  TOP w11.81: J1.1@151.18,401.18 151.57,400.79 214.1,400.79 221.5,393.39 236.88,393.39 v1(237.64,392.64) ; D2.A@240.35,150.39 241.83,148.92 271.08,148.92 v1(271.83,148.17)
  SIG w11.81: v1(271.83,148.17) 319.72,100.28 626.32,100.28 632,94.6 862.32,94.6 886.11,118.39 1034.31,118.39 1034.48,118.23 1147.41,118.23 1153.44,124.26 1158.94,129.76 1158.94,165.51 1148.03,176.42 v1(1148.03,177.49)
  BOTTOM w11.81: v1(237.64,392.64) 271.83,358.44 v1(271.83,148.17) ; v1(1148.03,177.49) 1149.09,177.49 1158.61,187.01 1258.54,187.01 SJ1.1@1270,198.46
pads on no net: Fiducial_2.1 J1.4 JP2.3 U1.21 U2.5 U2.11 U2.15 U2.20 U2.24 U2.25 U2.32 U2.33 U4.1 U4.2 U4.3 U4.7 U4.9 U5.A2 U5.A5 U5.A6 U5.B1 U5.B6 U5.C1 U5.C6 U5.D1 U5.D6 U5.E1 U5.E6 U5.F2 U5.F5 U6.6 U9.9 U9.10 U9.11

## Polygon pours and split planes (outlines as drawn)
no net on Top Overlay "GND_SILK" (solid): 1198.82,700 1198.82,585.83 1297.24,585.83 1297.24,700 1281.38,700 1281.38,648.82 cw(c1250.3,649.11) 1250.01,618.03 cw(c1249.11,649.71) 1217.44,648.82 1217.44,700
no net on Top Overlay "GND_SILK" (solid): 1500,0 1500,114.17 1401.57,114.17 1401.57,0 1417.44,0 1417.44,51.18 cw(c1448.51,50.89) 1448.81,81.97 cw(c1449.71,50.29) 1481.38,51.18 1481.38,0
GND on TOP "GND_TOP" (solid, remove dead copper, pour order 1): 0,0 0,700 1700,700 1700,0
GND on GND "GND_2" (solid, remove dead copper, pour order 0): 0,700 0,0 1700,0 1700,700
+3V3 on SIG "PWR" (solid, remove dead copper, pour order 3): 0,0 0,700 1700,700 1700,0
GND on BOTTOM "GND_BOT" (solid, remove dead copper, pour order 4): 0,0 0,700 1700,700 1700,0

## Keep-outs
SIG:
  region: 386.22,388.78 331.1,388.78 331.1,334.97 374.27,334.97 443.93,265.31 577.62,265.31 637.61,205.32 834.58,205.32 834.58,251.44 834.1,251.92 674.99,251.92 618.39,308.52 466.47,308.52

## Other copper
TOP:
  pour cut-out: 598.98,381.71 598.98,328.85 605.26,322.57 637.92,322.57 670.66,289.83 710.55,289.83 713.98,293.26 713.98,346.7 739.37,372.09 739.37,390.16 605.02,390.16 601.67,386.81
  pour cut-out: 1699.29,162.89 1549.29,162.89 1549.29,536.73 1699.29,536.73
GND:
  pour cut-out: 1699.29,162.89 1549.29,162.89 1549.29,536.73 1699.29,536.73
SIG:
  pour cut-out: 1699.29,162.89 1549.29,162.89 1549.29,536.73 1699.29,536.73
BOTTOM:
  pour cut-out: 1270.08,190.35 1235.81,190.35 1235.81,131.54 1270,131.54
  pour cut-out: 1578.74,625.98 1610.24,625.98 1610.24,688.98 1578.74,688.98
  pour cut-out: 1699.29,162.89 1549.29,162.89 1549.29,536.73 1699.29,536.73
  text "..." at 1602.36,633.86 h15.75 r90

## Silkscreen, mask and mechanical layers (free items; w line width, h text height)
Top Overlay:
  drawing of 10 lines, arcs and shapes, not listed
  text "." at 1127.8,598.27 h3.94 r90
  text "." at 554.96,472.28 h3.94 r90
  text "." at 310.87,434.88 h3.94 r90
  text "." at 507.72,234.09 h3.94 r90
Bottom Overlay:
  drawing of 235 lines, arcs and shapes, not listed
Bottom Solder:
  rectangle: 606.04,239.57 682.7,297.44
Top 3D Body:
  the board outline again, w0.39
Route Tool Path:
  lines w78.74: -39.37,39.37 -39.37,0 ccw(c0,0) 0,-39.37 1700,-39.37 ccw(c1700,0) 1739.37,0 1739.37,255.91 ; -39.37,196.85 -39.37,511.81 ; -39.37,669.29 -39.37,700 cw(c0,700) 0,739.37 1700,739.37 cw(c1700,700) 1739.37,700 1739.37,413.39
Board:
  the board outline again, w3.94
